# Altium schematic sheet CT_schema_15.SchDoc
size 388 x 278 mm
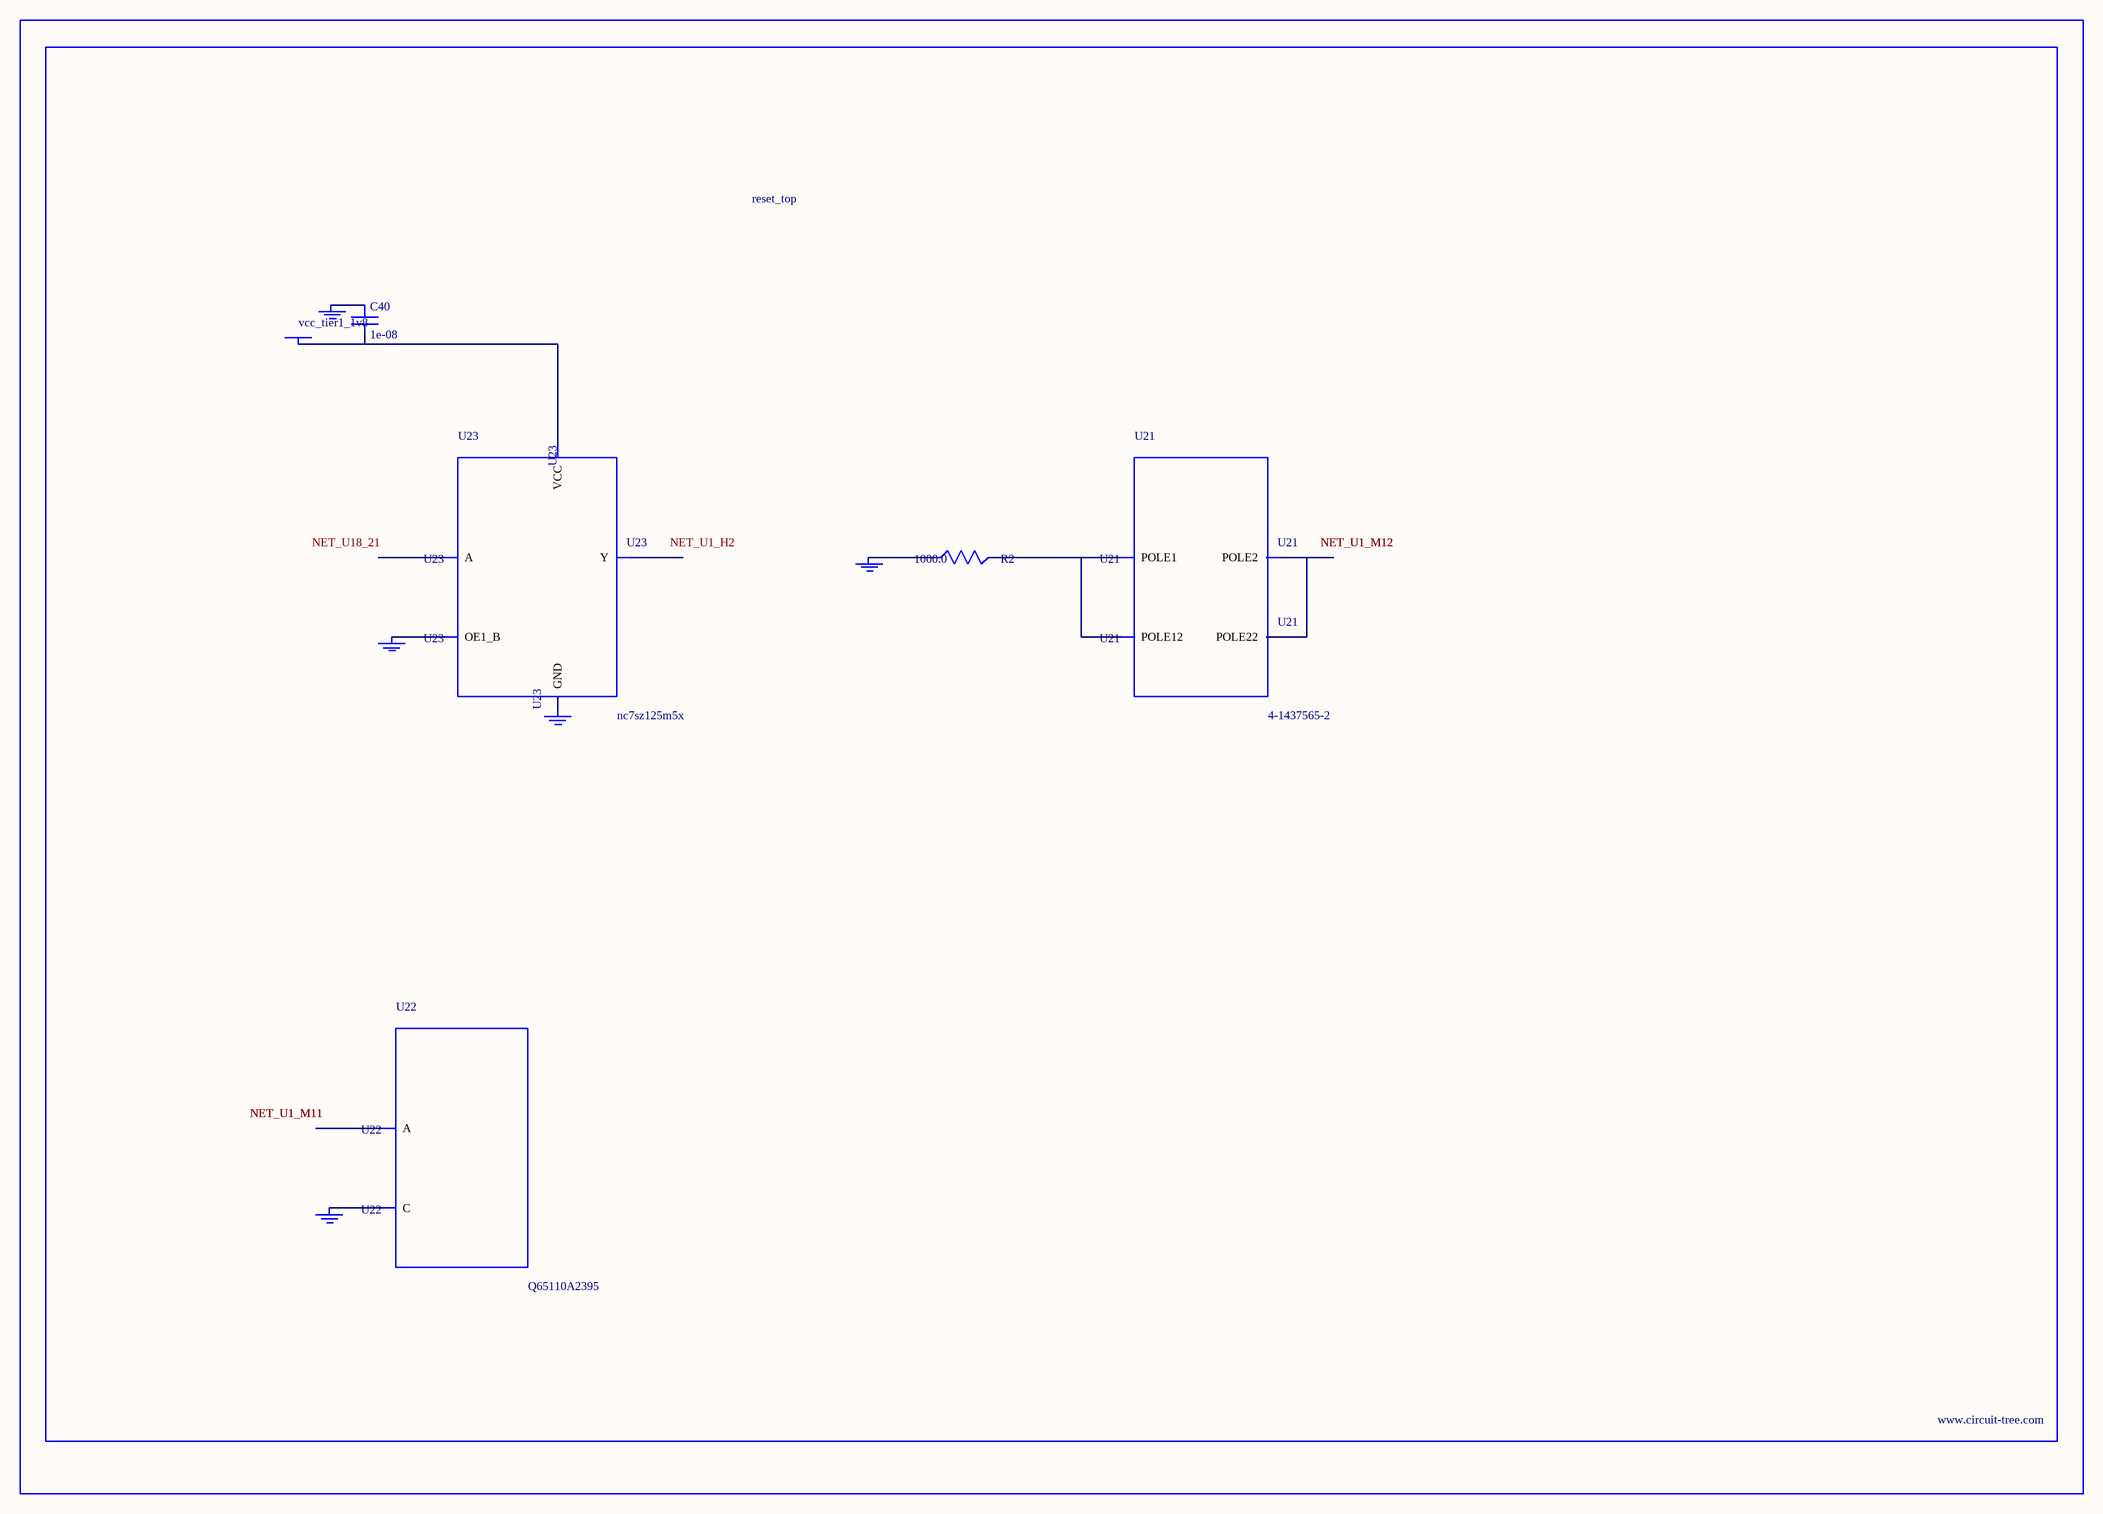
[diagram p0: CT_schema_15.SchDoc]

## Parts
BORDER14  (no value)
C40  1e-08  [C0402]
GND_INSTANCE_14_0  (no value)
GND_INSTANCE_14_1  (no value)
GND_INSTANCE_14_2  (no value)
GND_INSTANCE_14_3  (no value)
GND_INSTANCE_14_4  (no value)
POWER_INSTANCE_14_0  vcc_tier1_1v8
R2  1000.0  [R0603]
U21  4-1437565-2  [SW_4-1437565-2]
U22  Q65110A2395  [LGM67K-G1J2-24-Z]
U23  nc7sz125m5x  [NC7SZ125M5X]

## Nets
NetC40_1: C40.1 GND_INSTANCE_14_2.0(GND)
NetC40_2: C40.2 POWER_INSTANCE_14_0.0(PWR) U23.5(VCC)
NetGND_INSTANCE_14_0_0: GND_INSTANCE_14_0.0(GND) R2.1
NetGND_INSTANCE_14_1_0: GND_INSTANCE_14_1.0(GND) U22.C
NetGND_INSTANCE_14_3_0: GND_INSTANCE_14_3.0(GND) U23.1(OE1_B)
NetGND_INSTANCE_14_4_0: GND_INSTANCE_14_4.0(GND) U23.3(GND)
NetR2_2: R2.2 U21.1(POLE1) U21.2(POLE12)
NetU21_3: U21.3(POLE2) U21.4(POLE22)

Not connected (* = marked no-connect by the designer): U22 A; U23 2(A) 4(Y)

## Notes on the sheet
- Labels drawn without touching a wire or pin: NET_U1_H2, NET_U18_21

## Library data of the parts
BORDER14 = BORDER_PAGE14
C40 = C0402C103K3RAC
GND_INSTANCE_14_0-GND_INSTANCE_14_4 = GND
POWER_INSTANCE_14_0 = PWR
R2 = RC0603JR-071KL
